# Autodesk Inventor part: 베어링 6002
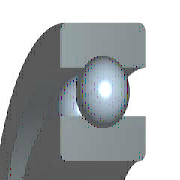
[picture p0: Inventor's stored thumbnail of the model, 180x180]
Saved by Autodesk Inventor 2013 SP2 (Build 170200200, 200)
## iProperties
Created: 2009-02
Part Number: 베어링 6002
Material: 강, 연강
Description: 깊은 그루브 볼 베어링
Document SubType Name: Modeling
Standard: KS B 2023
Designer: SeoGD™[esajin.kr]
Standards Organization: KS
Language: ko-KR
Size Designation: 6002 - 15 x 32 x 9
Categories: <MemberInstance><Categories><Category DisplayName="샤프트 부품" InternalName="7f7aeb1f-a693-4053-b835-cee3144e0d98" Mnemonic="SHFT"><Category DisplayName="베어링" Inter
Density: 1 g/cm^3
IsCustomPart: 1
Author: SeoGD™[esajin.kr]
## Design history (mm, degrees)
sketch "스케치" dims "d0" = 4.42 (= -0.26 x WD + 0.26 x BD)
  geometry: L1 (2.29, 11.75)-(6.71, 11.75); L2 (4.5, 11.75)-(4.5, 9.54); L3 (4.5, 11.75)-(4.5, 13.96); L4 (2.858, 10.271)-(0, 10.271); L5 (0, 7.5)-(9, 7.5); L6 (2.858, 13.229)-(0, 13.229); L7 (0, 16)-(9, 16); L8 (9, 7.5)-(9, 10.271); L9 (6.142, 10.271)-(9, 10.271); L10 (6.142, 13.229)-(9, 13.229); L11 (9, 16)-(9, 13.229); L12 (-1.4, 0)-(8.4, 0) reference; L13 (0, -0.3)-(0, 5.3) reference
  constraints: 22 end point, 4 point on line, 2 collinear, 2 perpendicular, 2 symmetric about line, 1 midpoint, 1 parallel, 14 other
  dimensions: "d9" = 15 diameter of L5 L12 (= WD); "d11" = 32 diameter of L7 L12 (= BD); "d12" = 9 distance between parallel lines of L8 L13 (= KB); "d13" = 20.542 diameter of L9 L12 (= 0.326 x BD + 0.674 x WD)
revolve "본체" stored, may be unused: angle "d6" = 90 deg
revolve "볼" stored, may be unused: angle "d7" = 90 deg
pattern_circular "IDS_ARRAYBALL[SIMPL:T]" dims angle "d3" = 360 deg
body "Solid1"
fillet "모깎기1" dims "d1" = 0.3 (= KRS)
other parameters: "WD" = 15 [user parameter; used in 5 equation terms], "BD" = 32 [user parameter; used in 5 equation terms], "KB" = 9 [user parameter; used in 1 equation term], "KRS" = 0.3 [user parameter; used in 1 equation term], "d4" = 0, "d5" = 0, "d8" = 0, "d14" = 0, "d15" = 0, "BBA" = 0 [user parameter], "BC0" = 2850000 [user parameter], "BC" = 5590000 [user parameter], "BR" = 16 (= 0.5 x BD) [user parameter], "WR" = 7.5 (= 0.5 x WD) [user parameter]
